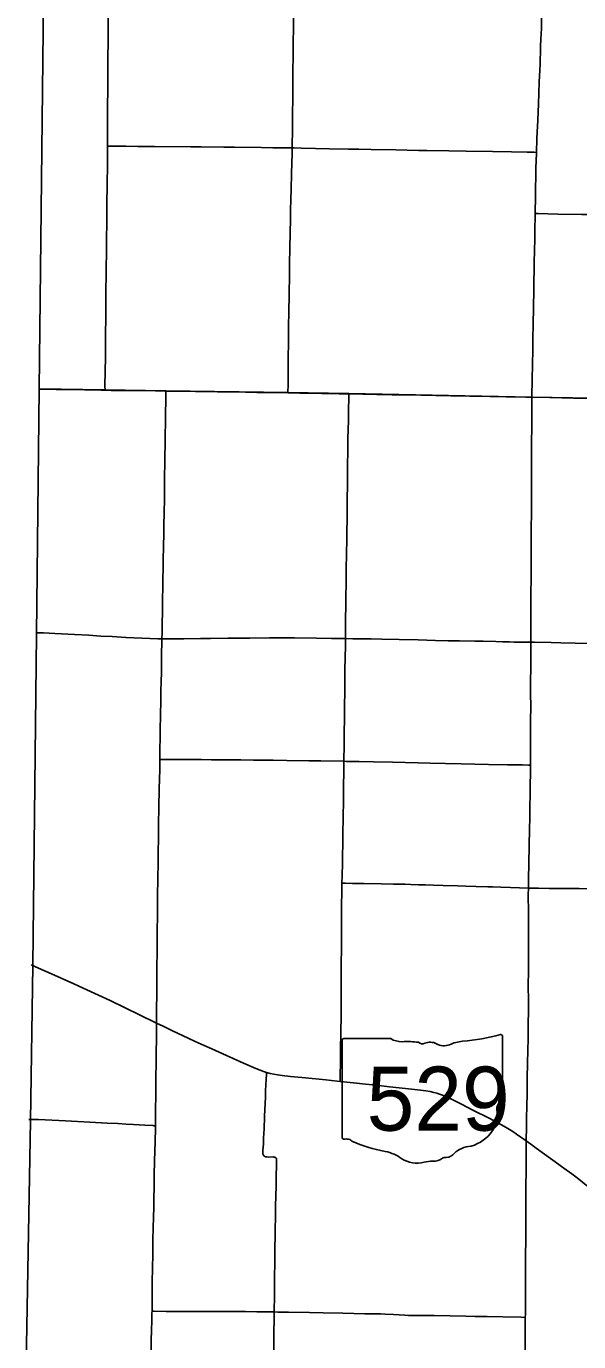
# Model space of a CAD drawing. Extents: x 1815539 to 1947826, y 273303 to 993194.
# Drawn here: x 1840970 to 1852961, y 911339 to 939932 of the extents above; entities that cross this region are included whole.
import ezdxf

# ---------------------------------------------------------------- set-up
doc = ezdxf.new("R2010")
doc.units = 0
for name, color, linetype in [('GM_X_County', 7, 'Continuous'), ('GM_X_County_Road', 7, 'Continuous'), ('GM_X_State_Route', 7, 'Continuous'), ('GM_X_Township', 7, 'Continuous'), ('GM_X_Township_Road', 7, 'Continuous'), ('SC_Shading3', 7, 'Continuous')]:
    doc.layers.add(name, color=color, linetype=linetype)

msp = doc.modelspace()

# ---------------------------------------------------------------- linework, layer by layer
at = {"layer": 'GM_X_County'}
msp.add_lwpolyline([(1840970, 910855), (1841058, 916141), (1841113, 919520), (1841192, 926713), (1841249, 932050), (1841362, 942439)], dxfattribs=at)
at = {"layer": 'GM_X_County_Road'}
for points in [[(1846744, 937289), (1846745, 937386), (1846749, 937632), (1846751, 937879), (1846755, 938518), (1846759, 938879), (1846764, 939371), (1846766, 939650), (1846769, 939830), (1846771, 939945), (1846771, 940142), (1846772, 940470), (1846776, 940765), (1846777, 940978), (1846779, 941142), (1846780, 941405), (1846782, 941634), (1846785, 941946), (1846787, 942126), (1846788, 942340), (1846790, 942611)], [(1852044, 937191), (1852056, 937496), (1852072, 937889), (1852087, 938250), (1852096, 938479), (1852106, 938725), (1852116, 938971), (1852122, 939119), (1852126, 939233), (1852130, 939348), (1852136, 939495), (1852143, 939659), (1852146, 939758), (1852151, 939889), (1852157, 940217)], [(1846649, 931965), (1846651, 932155), (1846654, 932401), (1846665, 933385), (1846670, 933746), (1846674, 934074), (1846678, 934254), (1846681, 934386), (1846681, 934582), (1846686, 934812), (1846689, 935074), (1846698, 935484), (1846702, 935698), (1846707, 935927), (1846714, 936173), (1846720, 936386), (1846730, 936731), (1846742, 937173), (1846744, 937289)], [(1846744, 937289), (1846783, 937289), (1846946, 937285), (1847553, 937272), (1847962, 937264), (1848192, 937258), (1848454, 937254), (1848995, 937244), (1849486, 937234), (1849666, 937232), (1850142, 937225), (1850519, 937218), (1851092, 937209), (1851502, 937202), (1851846, 937196), (1851994, 937194), (1852044, 937191)], [(1852018, 935862), (1852023, 936250), (1852027, 936430), (1852031, 936643), (1852035, 936856), (1852043, 937168), (1852044, 937191)], [(1851948, 931868), (1851948, 931903), (1851953, 932248), (1851960, 932592), (1851963, 932888), (1851968, 933134), (1851971, 933462), (1851978, 933806), (1851985, 934216), (1851996, 934807), (1852002, 935053), (1852008, 935315), (1852010, 935528), (1852016, 935790), (1852018, 935862)], [(1841253, 932045), (1841389, 932043), (1841620, 932039), (1842230, 932030), (1842593, 932024), (1842679, 932023)], [(1842679, 932023), (1842809, 932019), (1843235, 932014), (1843777, 932005), (1844001, 932003)], [(1844001, 932003), (1844137, 932002), (1844416, 931998), (1844646, 931997), (1844826, 931993), (1845121, 931987), (1845728, 931978), (1845974, 931975), (1846220, 931972), (1846450, 931969), (1846649, 931965)], [(1846649, 931965), (1846909, 931960), (1847139, 931956), (1847385, 931952), (1847762, 931946), (1847973, 931942)], [(1847973, 931942), (1848582, 931932), (1848910, 931925), (1849205, 931920), (1849533, 931912), (1850189, 931901), (1850386, 931897), (1850599, 931894), (1851042, 931886), (1851386, 931879), (1851813, 931871), (1851948, 931868)], [(1851922, 926543), (1851922, 926720), (1851923, 926933), (1851924, 927015), (1851924, 927130), (1851925, 927294), (1851926, 927622), (1851926, 927687), (1851927, 927851), (1851927, 928540), (1851930, 928885), (1851934, 929492), (1851934, 929820), (1851939, 930492), (1851941, 930870), (1851944, 931231), (1851946, 931477), (1851947, 931706), (1851948, 931868)], [(1851948, 931868), (1852338, 931860), (1852846, 931850), (1853223, 931841), (1853277, 931840)], [(1843868, 923997), (1843868, 924000), (1843872, 924230), (1843875, 924459), (1843878, 924607), (1843884, 924984), (1843888, 925246), (1843893, 925475), (1843898, 925705), (1843901, 925869), (1843904, 926016), (1843908, 926279), (1843914, 926557), (1843915, 926616)], [(1843915, 926616), (1844130, 926614), (1844392, 926616), (1844754, 926622), (1844967, 926626), (1845345, 926630), (1845575, 926633), (1845821, 926635), (1846248, 926640), (1846544, 926641), (1846790, 926639), (1847267, 926632), (1847595, 926626), (1847897, 926623)], [(1847865, 923956), (1847865, 924041), (1847869, 924238), (1847869, 924337), (1847872, 924468), (1847872, 924567), (1847876, 924895), (1847879, 925191), (1847884, 925437), (1847888, 925946), (1847897, 926471), (1847897, 926623)], [(1851917, 923869), (1851917, 923882), (1851918, 923981), (1851918, 924145), (1851918, 924293), (1851919, 924785), (1851920, 925195), (1851919, 925375), (1851918, 925457), (1851918, 925572), (1851919, 925703), (1851921, 925982), (1851921, 926474), (1851922, 926543)], [(1843817, 920623), (1843817, 920640), (1843820, 920984), (1843825, 921443), (1843829, 921722), (1843832, 921951), (1843839, 922312), (1843843, 922591), (1843849, 922951), (1843856, 923361), (1843860, 923558), (1843865, 923787), (1843868, 923997)], [(1847821, 921305), (1847824, 921463), (1847831, 921742), (1847837, 921956), (1847840, 922103), (1847843, 922317), (1847852, 922793), (1847855, 923056), (1847857, 923302), (1847864, 923844), (1847865, 923956)], [(1847865, 923956), (1847919, 923954), (1847984, 923953), (1848198, 923949), (1848509, 923942), (1848919, 923933), (1849477, 923920), (1849740, 923916), (1850068, 923910), (1850412, 923902), (1851003, 923888), (1851413, 923880), (1851741, 923876), (1851872, 923871), (1851917, 923869)], [(1851869, 921200), (1851872, 921308), (1851874, 921390), (1851875, 921521), (1851876, 921603), (1851883, 921832), (1851886, 922013), (1851889, 922209), (1851891, 922390), (1851899, 922816), (1851902, 922997), (1851906, 923210), (1851910, 923423), (1851915, 923718), (1851917, 923869)], [(1847821, 921305), (1847890, 921303), (1848054, 921300), (1848300, 921296), (1848678, 921290), (1848940, 921286), (1849186, 921281), (1849318, 921278), (1849482, 921272), (1849629, 921268), (1849810, 921263), (1850023, 921257), (1850335, 921248), (1850515, 921243), (1850728, 921235), (1850991, 921228), (1851089, 921224), (1851270, 921219), (1851482, 921213), (1851679, 921206), (1851869, 921200)], [(1851823, 915703), (1851824, 915795), (1851827, 915928), (1851832, 916223), (1851836, 916437), (1851840, 916748), (1851842, 917076), (1851847, 917388), (1851856, 917683), (1851863, 917913), (1851865, 918060), (1851868, 918241), (1851870, 918536), (1851869, 918717), (1851868, 919110), (1851869, 919373), (1851869, 919701), (1851869, 919996), (1851869, 920177), (1851870, 920258), (1851869, 920455), (1851870, 920652), (1851867, 921078), (1851869, 921177), (1851869, 921200)], [(1851869, 921200), (1851925, 921198), (1852089, 921195), (1852319, 921193), (1852696, 921189), (1852975, 921187), (1853287, 921182), (1853550, 921180), (1853763, 921178), (1854009, 921176), (1854190, 921173), (1854485, 921168), (1854863, 921162), (1855224, 921154), (1855273, 921153)], [(1843798, 918263), (1843797, 918443), (1843801, 919017), (1843806, 919509), (1843808, 919788), (1843810, 920017), (1843812, 920247), (1843817, 920623)]]:
    msp.add_lwpolyline(points, dxfattribs=at)
at = {"layer": 'GM_X_State_Route'}
for points in [[(1841073, 919533), (1841234, 919461), (1841519, 919333), (1841999, 919118), (1842283, 918989), (1842536, 918872), (1842789, 918753), (1843115, 918596), (1843410, 918453), (1843798, 918263), (1843942, 918197), (1844146, 918098), (1844486, 917935), (1844636, 917868), (1844831, 917781), (1844995, 917706), (1845235, 917598), (1845683, 917395), (1845953, 917276), (1846044, 917238), (1846122, 917210), (1846185, 917190), (1846264, 917169), (1846345, 917152), (1846426, 917139), (1846524, 917125), (1846703, 917105), (1847030, 917072), (1847471, 917028), (1847715, 917003), (1847782, 916995), (1848074, 916964), (1848335, 916936), (1848564, 916912), (1848857, 916879), (1849200, 916843), (1849526, 916807), (1849640, 916792), (1849737, 916775), (1849817, 916758), (1849880, 916742), (1849943, 916722), (1850004, 916700), (1850080, 916669), (1850155, 916635), (1850272, 916577), (1850418, 916502), (1850666, 916375), (1851017, 916195), (1851192, 916104), (1851336, 916027), (1851421, 915977), (1851533, 915908), (1851614, 915853), (1851823, 915703), (1851921, 915633), (1852040, 915547), (1852533, 915192), (1852590, 915151)], [(1852590, 915151), (1852693, 915077), (1852812, 914989), (1852927, 914898), (1853042, 914804), (1853157, 914711), (1853248, 914641), (1853341, 914574), (1853450, 914500), (1853601, 914402), (1853643, 914374)]]:
    msp.add_lwpolyline(points, dxfattribs=at)
at = {"layer": 'GM_X_Township'}
msp.add_lwpolyline([(1862681, 942300), (1862643, 939637), (1862581, 935266), (1862529, 931646), (1857238, 931762), (1853272, 931847), (1851942, 931872), (1847971, 931949), (1846644, 931971), (1843997, 932010), (1842672, 932027), (1841249, 932050)], dxfattribs=at)
at = {"layer": 'GM_X_Township_Road'}
for points in [[(1842730, 937328), (1842731, 937497), (1842732, 937907), (1842735, 938153), (1842739, 938596), (1842740, 938875), (1842741, 939072), (1842743, 939252), (1842745, 939597), (1842748, 940007), (1842748, 940269), (1842750, 940762), (1842751, 941073), (1842752, 941303), (1842754, 941828), (1842755, 942287), (1842755, 942452), (1842755, 942519)], [(1842679, 932023), (1842677, 932119), (1842686, 932743), (1842688, 932972), (1842689, 933102), (1842690, 933297), (1842693, 933543), (1842695, 933724), (1842697, 934003), (1842705, 934708), (1842709, 934987), (1842714, 935348), (1842715, 935627), (1842718, 935955), (1842721, 936184), (1842724, 936365), (1842727, 936595), (1842729, 936824), (1842730, 937136), (1842730, 937328)], [(1842730, 937328), (1842768, 937327), (1842801, 937326), (1842949, 937325), (1843129, 937324), (1843391, 937321), (1843751, 937318), (1844538, 937313), (1844767, 937310), (1845258, 937305), (1845488, 937302), (1846077, 937298), (1846323, 937294), (1846744, 937289)], [(1852018, 935862), (1852064, 935861), (1852080, 935861), (1852294, 935855), (1852507, 935852), (1853032, 935844), (1853213, 935841), (1853328, 935839), (1853705, 935834), (1853745, 935833)], [(1843915, 926616), (1843917, 926759), (1843918, 926939), (1843923, 927218), (1843925, 927365), (1843927, 927480), (1843933, 927742), (1843943, 928332), (1843948, 928627), (1843953, 928905), (1843957, 929118), (1843961, 929331), (1843967, 929691), (1843972, 930035), (1843979, 930543), (1843985, 930887), (1843994, 931477), (1843999, 931837), (1844001, 931966), (1844001, 931968), (1844001, 932003)], [(1847897, 926623), (1847901, 927101), (1847903, 927282), (1847908, 927528), (1847912, 927823), (1847916, 928085), (1847922, 928512), (1847925, 928742), (1847928, 928889), (1847932, 929283), (1847936, 929611), (1847941, 930005), (1847945, 930431), (1847949, 930661), (1847953, 930973), (1847961, 931366), (1847965, 931563), (1847972, 931886), (1847973, 931908), (1847973, 931942)], [(1841177, 926746), (1841346, 926745), (1841592, 926734), (1842018, 926710), (1842329, 926694), (1842591, 926679), (1842836, 926666), (1843131, 926650), (1843475, 926633), (1843828, 926618), (1843915, 926616)], [(1847897, 926623), (1848062, 926621), (1848456, 926614), (1848686, 926610), (1849063, 926602), (1849474, 926593), (1849851, 926583), (1850130, 926577), (1850376, 926571), (1850704, 926567), (1850885, 926564), (1851164, 926557), (1851312, 926554), (1851445, 926550), (1851461, 926550), (1851559, 926548), (1851773, 926545), (1851887, 926543), (1851922, 926543)], [(1851922, 926543), (1852002, 926543), (1852363, 926536), (1852576, 926532), (1852888, 926526), (1853200, 926519), (1853692, 926510), (1853888, 926505), (1853919, 926504)], [(1843868, 923997), (1843921, 923996), (1843937, 923996), (1844167, 923993), (1844347, 923993), (1844773, 923992), (1844987, 923990), (1845216, 923989), (1845626, 923985), (1845905, 923983), (1846331, 923978), (1846626, 923975), (1847102, 923968), (1847364, 923964), (1847865, 923956)], [(1847782, 916995), (1847782, 917047), (1847783, 917162), (1847788, 917375), (1847791, 917604), (1847800, 918145), (1847802, 918342), (1847805, 918588), (1847807, 918785), (1847808, 919113), (1847807, 919326), (1847807, 919441), (1847806, 919621), (1847809, 919818), (1847809, 919933), (1847812, 920195), (1847812, 920359), (1847816, 920753), (1847818, 921179), (1847821, 921305)], [(1843771, 916033), (1843773, 916192), (1843774, 916356), (1843780, 916717), (1843785, 917110), (1843788, 917373), (1843791, 917619), (1843794, 917931), (1843797, 918177), (1843798, 918263)], [(1846138, 916134), (1846143, 916241), (1846160, 916651), (1846165, 916798), (1846169, 916913), (1846176, 917044), (1846183, 917142), (1846185, 917190)], [(1841024, 916170), (1841232, 916170), (1841822, 916138), (1842347, 916110), (1842724, 916092), (1842954, 916079), (1843134, 916069), (1843298, 916060), (1843544, 916046), (1843724, 916036), (1843741, 916035), (1843771, 916033)], [(1846351, 911985), (1846353, 912079), (1846355, 912259), (1846358, 912538), (1846360, 912784), (1846363, 913014), (1846367, 913408), (1846370, 913604), (1846371, 913719), (1846375, 913867), (1846377, 913965), (1846377, 914031), (1846379, 914162), (1846382, 914293), (1846392, 914720), (1846396, 914982), (1846400, 915130), (1846403, 915245), (1846402, 915278), (1846402, 915294), (1846399, 915312), (1846391, 915329), (1846382, 915339), (1846369, 915348), (1846354, 915353), (1846335, 915355), (1846220, 915352), (1846188, 915354), (1846171, 915356), (1846156, 915361), (1846141, 915369), (1846129, 915379), (1846118, 915392), (1846111, 915407), (1846107, 915422), (1846105, 915439), (1846106, 915472), (1846108, 915504), (1846116, 915635), (1846121, 915766), (1846130, 915963), (1846134, 916061), (1846138, 916134)], [(1843700, 912002), (1843703, 912075), (1843702, 912354), (1843704, 912633), (1843715, 913240), (1843719, 913551), (1843725, 913814), (1843730, 914043), (1843735, 914257), (1843740, 914486), (1843744, 914667), (1843748, 914962), (1843755, 915273), (1843765, 915683), (1843771, 915979), (1843771, 916033)], [(1851803, 911868), (1851804, 911941), (1851804, 912088), (1851804, 912351), (1851807, 912810), (1851808, 912941), (1851809, 913121), (1851810, 913269), (1851812, 913498), (1851812, 913711), (1851815, 914006), (1851816, 914613), (1851817, 914826), (1851818, 914941), (1851819, 915121), (1851820, 915334), (1851822, 915547), (1851823, 915646), (1851823, 915703)], [(1843673, 910654), (1843673, 910665), (1843674, 910829), (1843678, 911059), (1843683, 911370), (1843689, 911584), (1843693, 911797), (1843698, 911961), (1843700, 912002)], [(1843700, 912002), (1843742, 912001), (1844004, 911999), (1844300, 911999), (1844496, 911997), (1844726, 911996), (1844873, 911995), (1844988, 911994), (1845152, 911995), (1845382, 911993), (1845546, 911993), (1845726, 911992), (1845972, 911990), (1846071, 911988), (1846235, 911986), (1846351, 911985)], [(1846335, 908486), (1846333, 908570), (1846332, 908863), (1846331, 909077), (1846333, 909208), (1846337, 909700), (1846338, 909815), (1846342, 910192), (1846344, 910619), (1846342, 910799), (1846342, 910930), (1846343, 911177), (1846343, 911357), (1846343, 911521), (1846347, 911849), (1846351, 911985)], [(1846351, 911985), (1846431, 911984), (1846661, 911980), (1847120, 911972), (1847415, 911965), (1847842, 911958), (1848317, 911948), (1848481, 911945), (1848662, 911942), (1848760, 911939), (1848940, 911930), (1849186, 911915), (1849268, 911911), (1849366, 911910), (1849546, 911911), (1849825, 911908), (1850169, 911899), (1850514, 911892), (1850711, 911890), (1850973, 911884), (1851317, 911877), (1851711, 911869), (1851803, 911868)], [(1851791, 910839), (1851792, 910859), (1851794, 910908), (1851799, 911056), (1851801, 911531), (1851802, 911679), (1851803, 911868)]]:
    msp.add_lwpolyline(points, dxfattribs=at)
at = {"layer": 'SC_Shading3'}
for p, q in [((1847827, 917890), (1847827, 915777)), ((1848880, 917927), (1847861, 917927)), ((1851307, 916874), (1851307, 917979)), ((1851307, 916874), (1851307, 916874))]:
    msp.add_line(p, q, dxfattribs=at)
for centre, major_axis, start_param, end_param in [((1847867, 917895), (40.3, 0), 1.712693, 3.28349), ((1849123, 918172), (391, 0), 4.042523, 4.731795), ((1849253, 916740), (1404, 0), 1.404758, 1.657858), ((1849571, 917906), (113, 0), 3.836095, 5.185415), ((1849737, 917662), (235, 0), 0.950623, 2.079405), ((1850538, 917281), (743, 0), 1.699011, 2.107814), ((1850067, 920808), (3691, 0), 4.814394, 5.042369), ((1851269, 917984), (38.7, 0), 6.141152, 7.989035), ((1850040, 917997), (282, 0), 4.081561, 5.145723), ((1851298, 916792), (60, 0), 1.883978, 3.671073), ((1850917, 916653), (360, 0), 5.934695, 6.695948), ((1851266, 916869), (41.5, 0), 5.05454, 6.418171), ((1851446, 916411), (262, 0), 2.387724, 3.262537), ((1850274, 916270), (923, 0), 5.101752, 6.440018), ((1847867, 915773), (40.7, 0), 3.00124, 4.508301), ((1847873, 915989), (310, 0), 4.665946, 4.897461), ((1847937, 915655), (112, 0), 0.519207, 1.627899), ((1849350, 917554), (2665, 0), 4.195997, 4.488961), ((1850663, 915184), (506, 0), 1.647645, 2.488434), ((1848555, 914828), (834, 0), 0.823519, 1.323587), ((1849457, 915645), (529, 0), 4.026481, 4.996735), ((1849763, 914914), (435, 0), 1.495662, 1.94098), ((1849802, 915486), (282, 0), 4.691044, 5.507374), ((1850057, 915282), (79.4, 0), 1.147584, 2.315152), ((1850023, 915572), (298, 0), 4.937069, 5.64225)]:
    msp.add_ellipse(centre, major_axis=major_axis, ratio=0.8, start_param=start_param, end_param=end_param, dxfattribs=at)

# ---------------------------------------------------------------- texts
msp.add_text('529', height=1392.2, dxfattribs=at).set_placement((1848358, 915926))

doc.saveas('drawing.dxf')
